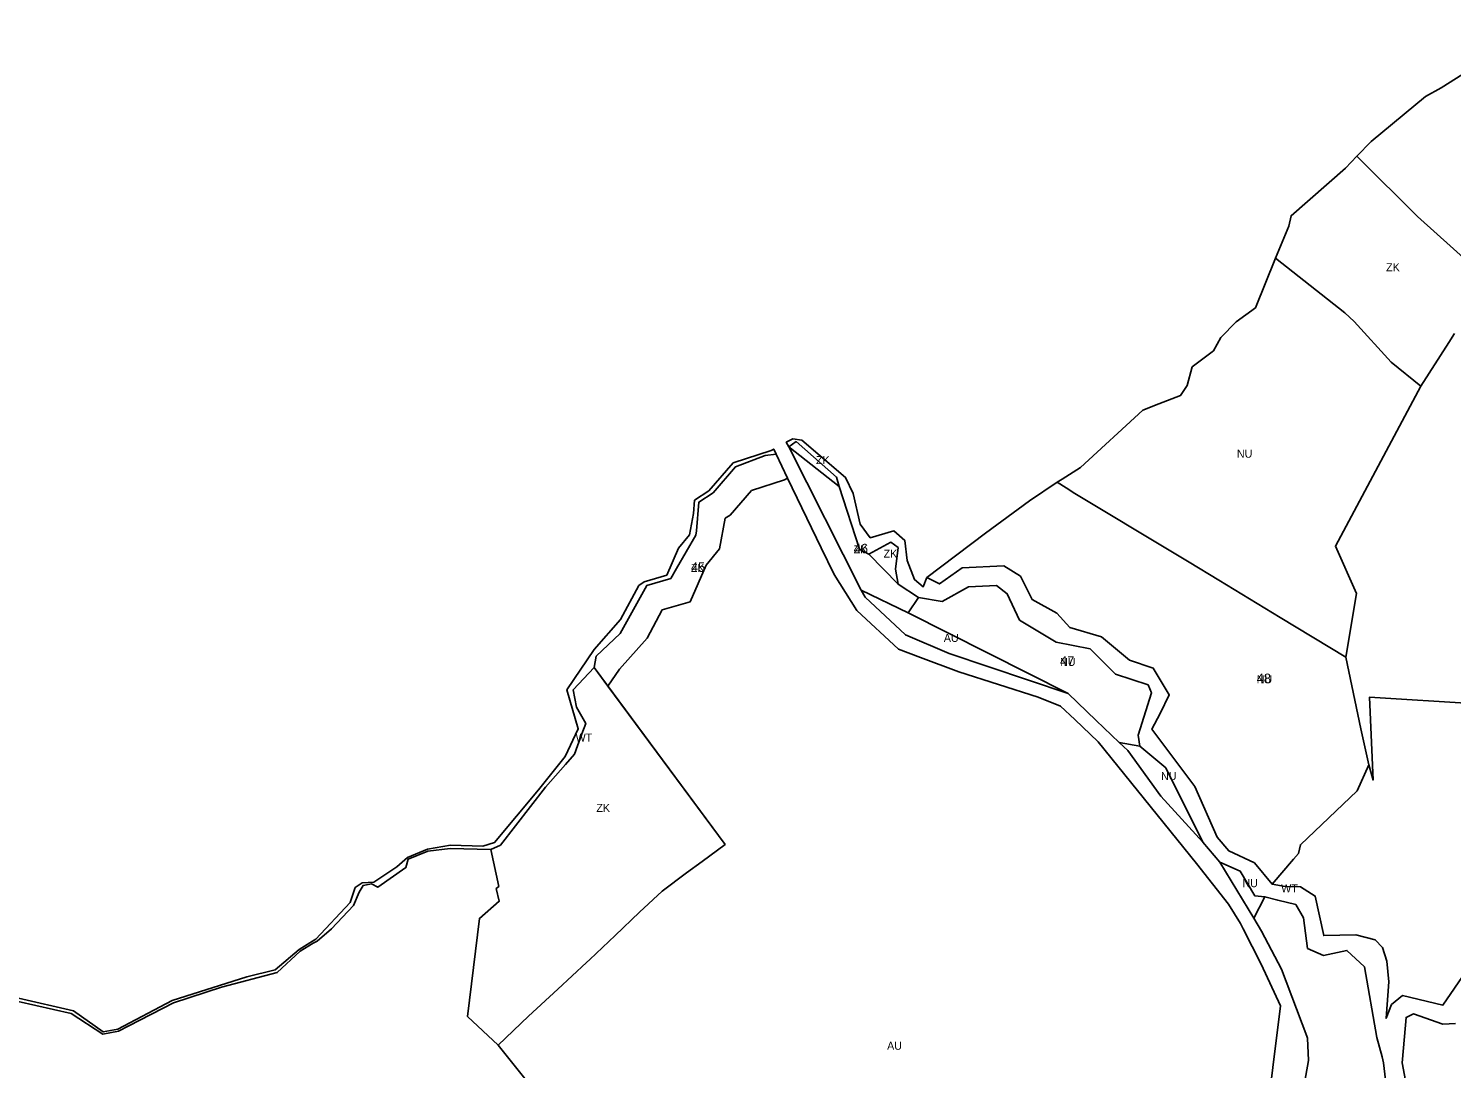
# Model space of a CAD drawing. Extents: x -521261 to -517465, y -1182764 to -1179456.
# Drawn here: x -520457 to -519568, y -1180356 to -1179707 of the extents above; entities that cross this region are included whole.
import ezdxf

# ---------------------------------------------------------------- set-up
doc = ezdxf.new("R2010")
doc.units = 0
for name, color, linetype in [('90640013', 7, 'Continuous'), ('90710013', 7, 'Continuous'), ('90710023', 7, 'Continuous'), ('90730013', 7, 'Continuous'), ('90730023', 7, 'Continuous'), ('90750013', 7, 'Continuous'), ('90770013', 7, 'Continuous'), ('ID_navrh', 7, 'Continuous')]:
    doc.layers.add(name, color=color, linetype=linetype)

msp = doc.modelspace()

# ---------------------------------------------------------------- linework, layer by layer
at = {"layer": '90640013'}
for points in [[(-519604.32, -1180407.52), (-519610.91, -1180352.92), (-519611.76, -1180349.16), (-519614.97, -1180337.01), (-519622.74, -1180292.93), (-519633.68, -1180282.66), (-519648.35, -1180285.79), (-519658.25, -1180281.44), (-519660.8, -1180262.28), (-519665.69, -1180254.02), (-519676.86, -1180251.38), (-519684.92, -1180249.16), (-519691.23, -1180248.49), (-519700.35, -1180233.19), (-519713.02, -1180227.59), (-519723.65, -1180215.01), (-519746.84, -1180168.57), (-519763.15, -1180155.18), (-519764.13, -1180148.17), (-519755.81, -1180121.7), (-519757.91, -1180116.91), (-519778.3, -1180110.21), (-519793.98, -1180094.42), (-519815.23, -1180090.06), (-519838.3, -1180076.34), (-519845.87, -1180059.96), (-519852.63, -1180054.73), (-519870.04, -1180055.63), (-519886.44, -1180064.71), (-519901.2, -1180062.26), (-519914.01, -1180053.95), (-519915.71, -1180044.57), (-519913.98, -1180031.05), (-519918.57, -1180027.76), (-519932.27, -1180035.16), (-519938.11, -1180032.03), (-519950.91, -1179992.96), (-519952.57, -1179987.21), (-519977.77, -1179964.92), (-519982.32, -1179968.2), (-519983.9, -1179965.28), (-519979.84, -1179963.1), (-519974.11, -1179964.05), (-519946.9, -1179987.22), (-519942.05, -1179997.35), (-519937.8, -1180016.46), (-519931.47, -1180024.91), (-519916.79, -1180020.7), (-519909.86, -1180026.63), (-519908.31, -1180039.25), (-519903.84, -1180051.08), (-519898.29, -1180055.51), (-519896.06, -1180049.84), (-519888.14, -1180053.8), (-519874.13, -1180043.77), (-519847.98, -1180042.57), (-519837.62, -1180048.87), (-519830.39, -1180063.53), (-519814.99, -1180072.13), (-519806.74, -1180080.96), (-519787.03, -1180086.82), (-519769.42, -1180101.42), (-519754.65, -1180106.41), (-519744.71, -1180123.1), (-519750.38, -1180134.69), (-519755.54, -1180144.42), (-519728.69, -1180180.4), (-519714.78, -1180211.92), (-519707.49, -1180220.58), (-519691.45, -1180227.98), (-519680.38, -1180241.32), (-519672.19, -1180242.7), (-519662.6, -1180243.02), (-519653.47, -1180248.7), (-519648.2, -1180273.36), (-519628.17, -1180272.86), (-519616, -1180276.16), (-519611.45, -1180280.78), (-519608.67, -1180289.34), (-519607.41, -1180302.24), (-519609.25, -1180325.08), (-519605.84, -1180316.47), (-519598.88, -1180310.89), (-519573.76, -1180316.82), (-519554.18, -1180288.28)], [(-520463.57, -1180312.56), (-520429.19, -1180320.47), (-520410.51, -1180333.56), (-520401.44, -1180331.81), (-520367.45, -1180313.88), (-520320.87, -1180299.08), (-520303.11, -1180294.79), (-520288.07, -1180282.2), (-520279.78, -1180276.87), (-520277.69, -1180275.6), (-520256.37, -1180252.84), (-520253.19, -1180243.42), (-520248.73, -1180240.4), (-520241.51, -1180240.05), (-520227.21, -1180230.49), (-520220.55, -1180224.59), (-520208.09, -1180219.42), (-520193.68, -1180216.96), (-520173.43, -1180217.54), (-520166.13, -1180215.24), (-520138.76, -1180182.47), (-520122.09, -1180161.67), (-520113.8, -1180144.2), (-520120.96, -1180119.91), (-520103.83, -1180094.71), (-520087.39, -1180076.07), (-520075.96, -1180054.84), (-520072.69, -1180052.42), (-520058.58, -1180048.36), (-520051.19, -1180031.41), (-520044.33, -1180023.1), (-520041.86, -1180009.79), (-520041.32, -1180001.52), (-520032.23, -1179995.56), (-520016.97, -1179978.11), (-519993.25, -1179970.43), (-519991.72, -1179969.54), (-519990.22, -1179972.72), (-519997.12, -1179973.52), (-520015.68, -1179980.65), (-520029.65, -1179996.94), (-520038.42, -1180002.72), (-520040.02, -1180020.63), (-520040.38, -1180023.43), (-520052.55, -1180044.22), (-520056.11, -1180050.48), (-520070.98, -1180054.76), (-520074.1, -1180060.33), (-520087.72, -1180084.77), (-520102.56, -1180098.8), (-520103.91, -1180106.03), (-520116.98, -1180120.03), (-520114.85, -1180130.78), (-520109.04, -1180140.91), (-520111.5, -1180147.38), (-520116.25, -1180160.07), (-520121.89, -1180166.52), (-520134.31, -1180180.81), (-520162.47, -1180216.91), (-520168.49, -1180219.56), (-520193.76, -1180219.08), (-520207.81, -1180220.75), (-520220.08, -1180225.72), (-520221.51, -1180230.96), (-520239.04, -1180243.26), (-520243.06, -1180241.12), (-520248.23, -1180242.09), (-520250.78, -1180246.3), (-520254.23, -1180254.59), (-520267.87, -1180269.14), (-520276.87, -1180276.89), (-520279.33, -1180278.11), (-520287.55, -1180283.14), (-520301.82, -1180296.57), (-520336.74, -1180305.65), (-520366.69, -1180315.44), (-520394.52, -1180329.87), (-520401.09, -1180333.16), (-520410.84, -1180334.99), (-520430.53, -1180322.01), (-520463.59, -1180314.64)], [(-519565.96, -1180328.26), (-519573.82, -1180328.67), (-519592.11, -1180322.38), (-519596.78, -1180324.51), (-519598.96, -1180350.54), (-519599.08, -1180352.83), (-519595.22, -1180373.94), (-519594.5, -1180398.05), (-519594.83, -1180406.45), (-519597.03, -1180421.15), (-519598.73, -1180433.05), (-519595.6, -1180440.97), (-519582.59, -1180451.31), (-519575.44, -1180455.06), (-519574.08, -1180456.6), (-519566.87, -1180468.21)]]:
    msp.add_lwpolyline(points, dxfattribs=at)
at = {"layer": '90710013'}
msp.add_lwpolyline([(-519566.55, -1179897.34), (-519570.09, -1179903.01), (-519587.53, -1179930.32), (-519606.04, -1179915.21), (-519629.1, -1179889.8), (-519635.04, -1179884.43), (-519678.25, -1179850.34), (-519670.03, -1179830.37), (-519668.57, -1179823.87), (-519634.54, -1179794.1), (-519627.405, -1179786.711), (-519626.2, -1179787.91), (-519589.63, -1179824.32), (-519556.92, -1179853.62)], dxfattribs=at)
for points in [[(-519950.91, -1179992.96), (-519982.32, -1179968.2), (-519977.77, -1179964.92), (-519952.57, -1179987.21)], [(-519932.27, -1180035.16), (-519918.57, -1180027.76), (-519913.98, -1180031.05), (-519915.71, -1180044.57), (-519914.01, -1180053.95)], [(-520182.93, -1180323.91), (-520175.62, -1180262.73), (-520163.16, -1180251.92), (-520165.16, -1180244.05), (-520163.46, -1180242.69), (-520168.49, -1180219.56), (-520162.47, -1180216.91), (-520134.31, -1180180.81), (-520121.89, -1180166.52), (-520116.25, -1180160.07), (-520111.5, -1180147.38), (-520109.04, -1180140.91), (-520114.85, -1180130.78), (-520116.98, -1180120.03), (-520103.91, -1180106.03), (-520022.17, -1180216.48), (-520036.42, -1180227.21), (-520046.22, -1180234.23), (-520061.32, -1180245.63), (-520075.57, -1180258.83), (-520090.76, -1180273.4), (-520106.59, -1180288.3), (-520108.66, -1180290.13), (-520126.56, -1180306.85), (-520144.91, -1180323.68), (-520163.84, -1180341.94)]]:
    msp.add_lwpolyline(points, close=True, dxfattribs=at)
at = {"layer": '90710023'}
for points in [[(-520087.997, -1180106.995), (-520095.274, -1180117.699), (-520103.91, -1180106.03), (-520102.56, -1180098.8), (-520087.72, -1180084.77), (-520074.1, -1180060.33), (-520070.98, -1180054.76), (-520056.11, -1180050.48), (-520052.55, -1180044.22), (-520040.38, -1180023.43), (-520040.02, -1180020.63), (-520038.42, -1180002.72), (-520029.65, -1179996.94), (-520015.68, -1179980.65), (-519997.12, -1179973.52), (-519990.22, -1179972.72), (-519983.059, -1179987.639), (-519985.048, -1179988.797), (-520005.552, -1179995.435), (-520018.976, -1180010.785), (-520022.081, -1180012.821), (-520025.61, -1180031.84), (-520033.979, -1180041.977), (-520044.007, -1180064.978), (-520061.398, -1180069.982), (-520070.87, -1180087.575)], [(-519907.69, -1180071.91), (-519937.13, -1180057.7), (-519982.32, -1179968.2), (-519950.91, -1179992.96), (-519938.11, -1180032.03), (-519932.27, -1180035.16), (-519914.01, -1180053.95), (-519901.2, -1180062.26)]]:
    msp.add_lwpolyline(points, close=True, dxfattribs=at)
at = {"layer": '90730013'}
for points in [[(-519587.53, -1179930.32), (-519640.83, -1180030.17), (-519627.78, -1180059.85), (-519634.46, -1180099.59), (-519675.47, -1180074.7), (-519713.64, -1180051.54), (-519732.23, -1180040.25), (-519741.66, -1180034.52), (-519803.62, -1179997.22), (-519808.96, -1179993.71), (-519814.62, -1179990.28), (-519811.48, -1179988.29), (-519800.15, -1179981.13), (-519761.18, -1179945.18), (-519751.14, -1179941.36), (-519737.63, -1179936.21), (-519733.58, -1179929.76), (-519730.34, -1179918.29), (-519717.08, -1179908.17), (-519712.36, -1179899.96), (-519702.87, -1179890.04), (-519690.81, -1179881.28), (-519678.25, -1179850.34), (-519635.04, -1179884.43), (-519629.1, -1179889.8), (-519606.04, -1179915.21)], [(-519749.89, -1180186.34), (-519770.6, -1180157.73), (-519775.91, -1180152.74), (-519763.15, -1180155.18), (-519746.84, -1180168.57), (-519723.65, -1180215.01)], [(-519684.92, -1180249.16), (-519691.85, -1180262.63), (-519713.02, -1180227.59), (-519700.35, -1180233.19), (-519691.23, -1180248.49)]]:
    msp.add_lwpolyline(points, close=True, dxfattribs=at)
at = {"layer": '90730023'}
for points in [[(-519619.93, -1180166.69), (-519627.35, -1180182.92), (-519662.7, -1180216.65), (-519664.04, -1180222.22), (-519667.04, -1180225.61), (-519680.38, -1180241.32), (-519691.45, -1180227.98), (-519707.49, -1180220.58), (-519714.78, -1180211.92), (-519728.69, -1180180.4), (-519755.54, -1180144.42), (-519750.38, -1180134.69), (-519744.71, -1180123.1), (-519754.65, -1180106.41), (-519769.42, -1180101.42), (-519787.03, -1180086.82), (-519806.74, -1180080.96), (-519814.99, -1180072.13), (-519830.39, -1180063.53), (-519837.62, -1180048.87), (-519847.98, -1180042.57), (-519874.13, -1180043.77), (-519888.14, -1180053.8), (-519896.06, -1180049.84), (-519859.45, -1180022.01), (-519831.9, -1180001.88), (-519814.62, -1179990.28), (-519808.96, -1179993.71), (-519803.62, -1179997.22), (-519741.66, -1180034.52), (-519732.23, -1180040.25), (-519713.64, -1180051.54), (-519675.47, -1180074.7), (-519634.46, -1180099.59), (-519624.93, -1180144.25)], [(-519807.85, -1180122.32), (-519907.69, -1180071.91), (-519901.2, -1180062.26), (-519886.44, -1180064.71), (-519870.04, -1180055.63), (-519852.63, -1180054.73), (-519845.87, -1180059.96), (-519838.3, -1180076.34), (-519815.23, -1180090.06), (-519793.98, -1180094.42), (-519778.3, -1180110.21), (-519757.91, -1180116.91), (-519755.81, -1180121.7), (-519764.13, -1180148.17), (-519763.15, -1180155.18), (-519775.91, -1180152.74), (-519790.242, -1180139.09)]]:
    msp.add_lwpolyline(points, close=True, dxfattribs=at)
at = {"layer": '90750013'}
for points in [[(-519556.92, -1179853.62), (-519589.63, -1179824.32), (-519626.2, -1179787.91), (-519627.405, -1179786.711), (-519618.53, -1179777.52), (-519584.53, -1179749.32), (-519574.82, -1179743.99), (-519516.1, -1179706.88)], [(-520126.31, -1180388.7), (-520163.84, -1180341.94), (-520144.91, -1180323.68), (-520126.56, -1180306.85), (-520108.66, -1180290.13), (-520106.59, -1180288.3), (-520090.76, -1180273.4), (-520075.57, -1180258.83), (-520061.32, -1180245.63), (-520046.22, -1180234.23), (-520036.42, -1180227.21), (-520022.17, -1180216.48), (-520095.274, -1180117.699), (-520087.997, -1180106.995), (-520070.87, -1180087.575), (-520061.398, -1180069.982), (-520044.007, -1180064.978), (-520033.979, -1180041.977), (-520025.61, -1180031.84), (-520022.081, -1180012.821), (-520018.976, -1180010.785), (-520005.552, -1179995.435), (-519985.048, -1179988.797), (-519983.059, -1179987.639), (-519962.14, -1180031.22), (-519954.08, -1180047.91), (-519939.79, -1180070.47), (-519913.72, -1180094.56), (-519900.11, -1180099.8), (-519876.16, -1180108.79), (-519826.58, -1180124.53), (-519812.65, -1180130.15), (-519803.64, -1180138.53), (-519789.06, -1180152.46), (-519727.7, -1180228.32), (-519707.67, -1180253.78), (-519700.26, -1180265.82), (-519698.4, -1180269.26), (-519687.23, -1180291.23), (-519675.24, -1180317.36), (-519684.8, -1180394.392)], [(-519554.18, -1180288.28), (-519573.76, -1180316.82), (-519598.88, -1180310.89), (-519605.84, -1180316.47), (-519609.25, -1180325.08), (-519607.41, -1180302.24), (-519608.67, -1180289.34), (-519611.45, -1180280.78), (-519616, -1180276.16), (-519628.17, -1180272.86), (-519648.2, -1180273.36), (-519653.47, -1180248.7), (-519662.6, -1180243.02), (-519672.19, -1180242.7), (-519680.38, -1180241.32), (-519667.04, -1180225.61), (-519664.04, -1180222.22), (-519662.7, -1180216.65), (-519627.35, -1180182.92), (-519619.93, -1180166.69), (-519617.36, -1180176.26), (-519619.68, -1180124.59), (-519552.72, -1180128.66)], [(-519660.39, -1180366.6), (-519657.79, -1180351.37), (-519658.29, -1180337.55), (-519658.78, -1180336.26), (-519674.66, -1180294.35), (-519686.99, -1180270.61), (-519691.85, -1180262.63), (-519684.92, -1180249.16), (-519676.86, -1180251.38), (-519665.69, -1180254.02), (-519660.8, -1180262.28), (-519658.25, -1180281.44), (-519648.35, -1180285.79), (-519633.68, -1180282.66), (-519622.74, -1180292.93), (-519614.97, -1180337.01), (-519611.76, -1180349.16), (-519610.91, -1180352.92), (-519604.32, -1180407.52)], [(-519543.828, -1180432.113), (-519595.6, -1180440.97), (-519598.73, -1180433.05), (-519597.03, -1180421.15), (-519594.83, -1180406.45), (-519594.5, -1180398.05), (-519595.22, -1180373.94), (-519599.08, -1180352.83), (-519598.96, -1180350.54), (-519596.78, -1180324.51), (-519592.11, -1180322.38), (-519573.82, -1180328.67), (-519565.96, -1180328.26)]]:
    msp.add_lwpolyline(points, dxfattribs=at)
msp.add_lwpolyline([(-519907.69, -1180071.91), (-519807.85, -1180122.32), (-519882.18, -1180097.21), (-519909.38, -1180085.67), (-519934.55, -1180062.12), (-519937.13, -1180057.7)], close=True, dxfattribs=at)
at = {"layer": '90770013'}
for points in [[(-519552.72, -1180128.66), (-519619.68, -1180124.59), (-519617.36, -1180176.26), (-519619.93, -1180166.69), (-519624.93, -1180144.25), (-519634.46, -1180099.59), (-519627.78, -1180059.85), (-519640.83, -1180030.17), (-519587.53, -1179930.32), (-519570.09, -1179903.01), (-519566.55, -1179897.34)], [(-520463.59, -1180314.64), (-520430.53, -1180322.01), (-520410.84, -1180334.99), (-520401.09, -1180333.16), (-520394.52, -1180329.87), (-520366.69, -1180315.44), (-520336.74, -1180305.65), (-520301.82, -1180296.57), (-520287.55, -1180283.14), (-520279.33, -1180278.11), (-520276.87, -1180276.89), (-520267.87, -1180269.14), (-520254.23, -1180254.59), (-520250.78, -1180246.3), (-520248.23, -1180242.09), (-520243.06, -1180241.12), (-520239.04, -1180243.26), (-520221.51, -1180230.96), (-520220.08, -1180225.72), (-520207.81, -1180220.75), (-520193.76, -1180219.08), (-520168.49, -1180219.56), (-520163.46, -1180242.69), (-520165.16, -1180244.05), (-520163.16, -1180251.92), (-520175.62, -1180262.73), (-520182.93, -1180323.91), (-520163.84, -1180341.94), (-520126.31, -1180388.7)]]:
    msp.add_lwpolyline(points, dxfattribs=at)

# ---------------------------------------------------------------- texts
at = {"layer": '90640013'}
for rotation, p in [(360, (-520115.478, -1180152.265)), (0, (-519674.767, -1180246.449))]:
    msp.add_text('WT', height=5, rotation=rotation, dxfattribs=at).set_placement(p)
at = {"layer": '90710013'}
for rotation, p in [(0, (-519609.224, -1179858.515)), (360, (-519965.308, -1179978.94)), (360, (-519923.125, -1180037.395)), (360, (-520102.55, -1180196.183))]:
    msp.add_text('ZK', height=5, rotation=rotation, dxfattribs=at).set_placement(p)
at = {"layer": '90710023'}
for rotation, p in [(360, (-519941.76, -1180034.71)), (0, (-520043.485, -1180046.256))]:
    msp.add_text('ZK', height=5, rotation=rotation, dxfattribs=at).set_placement(p)
at = {"layer": '90730013'}
for rotation, p in [(0, (-519702.414, -1179974.965)), (0, (-519749.78, -1180176.308)), (360, (-519698.97, -1180243.175))]:
    msp.add_text('NU', height=5, rotation=rotation, dxfattribs=at).set_placement(p)
at = {"layer": '90730023'}
for p in [(-519812.88, -1180104.955), (-519690.029, -1180115.8)]:
    msp.add_text('NU', height=5, rotation=360, dxfattribs=at).set_placement(p)
at = {"layer": '90750013'}
for p in [(-519885.496, -1180090.01), (-519920.91, -1180344.712)]:
    msp.add_text('AU', height=5, rotation=0, dxfattribs=at).set_placement(p)
at = {"layer": 'ID_navrh'}
msp.add_text('46', height=6, dxfattribs=at).set_placement((-519941.76, -1180034.71))
for s, rotation, p in [('45', 0, (-520043.485, -1180046.256)), ('47', 360, (-519812.88, -1180104.955)), ('48', 360, (-519690.029, -1180115.8))]:
    msp.add_text(s, height=6, rotation=rotation, dxfattribs=at).set_placement(p)

doc.saveas('drawing.dxf')
